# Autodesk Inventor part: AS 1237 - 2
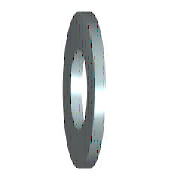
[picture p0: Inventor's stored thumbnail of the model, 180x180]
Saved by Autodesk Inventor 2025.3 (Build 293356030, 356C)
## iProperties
Created: 2024-01
Part Number: AS 1237 - 2
Material: Acciaio, Dolce
Description: Rondella piatta in metallo per uso ingegneristico generico (serie metrica)
Document SubType Name: Modeling
Standard: AS 1237
Designer: R5800u
Standards Organization: AS
Language: it-IT
Size Designation: 2
Categories: <MemberInstance><Categories><Category DisplayName="Elementi di fissaggio" InternalName="e4da775c-781d-43d5-af7c-5136215cf5a6" Mnemonic="FSTN"><Category DisplayN
Density: 7.85 g/cm^3
Appearance: Semilucidato
IsCustomPart: 0
Author: R5800u
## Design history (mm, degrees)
body "Solid1"
sketch "Schizzo"
  geometry: C1 r 2.25 at (0, 0); C2 r 1.1 at (0, 0); 1 further point
  constraints: 2 centre point, 2 coincident
  dimensions: "d0" = 2.2 diameter of C2 (= SD1); "d1" = 4.5 diameter of C1 (= SD2)
extrude "Corpo" new body sketch "Schizzo" distance "d2" = 0.3 (= SD); taper "d3" = 0 deg
workaxis "Work Axis1"
workplane "Work Plane1"
other parameters: "SD1" = 2.2 [user parameter; used in 1 equation term], "SD2" = 4.5 [user parameter; used in 1 equation term], "SD" = 0.3 [user parameter; used in 1 equation term], "d4" = 0, "d5" = 0, "d6" = 0, "d7" = 0, "NND" = 2 [user parameter]
